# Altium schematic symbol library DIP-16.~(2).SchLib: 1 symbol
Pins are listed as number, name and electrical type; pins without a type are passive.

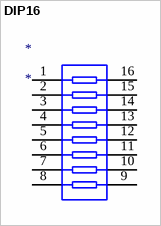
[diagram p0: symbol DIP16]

## DIP16
designator *
pins: 1, 2, 3, 4, 5, 6, 7, 8, 9, 10, 11, 12, 13, 14, 15, 16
